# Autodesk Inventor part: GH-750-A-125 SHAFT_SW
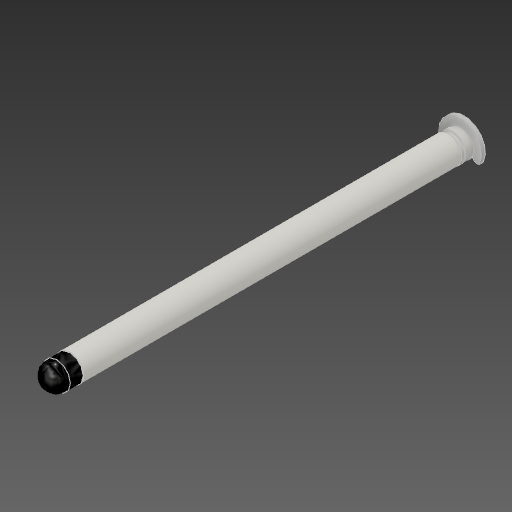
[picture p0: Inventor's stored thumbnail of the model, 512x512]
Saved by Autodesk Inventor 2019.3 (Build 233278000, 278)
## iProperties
Created: 2018-11
Part Number: GH-750-A-125 SHAFT_SW
Material: Generic
Document SubType Name: Modeling
Designer: Justin
Density: 1 g/cm^3
Appearance: Default
Author: Justin
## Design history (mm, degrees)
node "Assembly1" dims "d0" = 10
body "Solid1"
node "Part1:1" dims "d0" = 10
node "Part2:1" dims "d0" = 10
body "Solid2"
node "Part3:1" dims "d0" = 10
body "Solid3"
